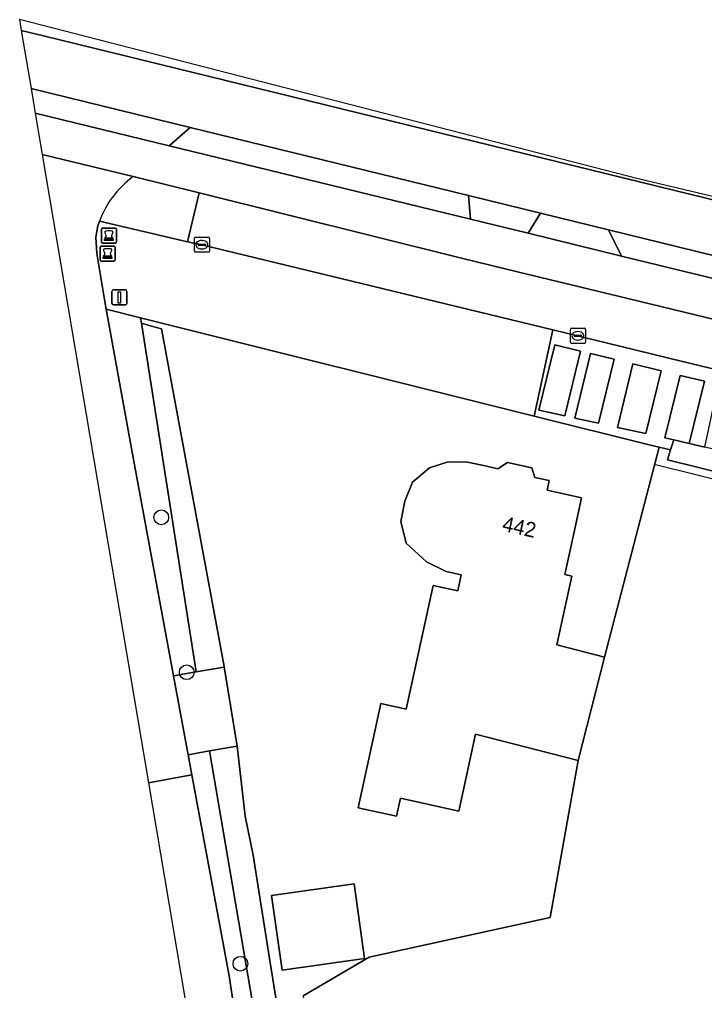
# Model space of a CAD drawing. Extents: x 163859 to 164644, y 379566 to 382155.
# Drawn here: x 164350.7 to 164396.2, y 382090.8 to 382155.2 of the extents above; entities that cross this region are included whole.
import ezdxf

# ---------------------------------------------------------------- set-up
doc = ezdxf.new("R2010")
doc.units = 0
for name, color, linetype in [('IMGEO_Berm_groen', 7, 'Continuous'), ('IMGEO_Bolder', 7, 'Continuous'), ('IMGEO_Boom', 7, 'Continuous'), ('IMGEO_Erf', 7, 'Continuous'), ('IMGEO_Fietspad_gesloten', 7, 'Continuous'), ('IMGEO_Fietspad_open', 7, 'Continuous'), ('IMGEO_Grasland_agrarisch', 7, 'Continuous'), ('IMGEO_Groenvoorziening', 7, 'Continuous'), ('IMGEO_Hek', 7, 'Continuous'), ('IMGEO_Kolk', 7, 'Continuous'), ('IMGEO_Pand', 7, 'Continuous'), ('IMGEO_Pand_nummerreeks', 7, 'Continuous'), ('IMGEO_Parkeervlak_open', 7, 'Continuous'), ('IMGEO_Rijbaan_lokaal_halfverhard', 7, 'Continuous'), ('IMGEO_Rijbaan_lokaal_open', 7, 'Continuous'), ('IMGEO_Rijbaan_regionaal_gesloten', 7, 'Continuous'), ('IMGEO_Verkeersbordpaal', 7, 'Continuous'), ('IMGEO_Verkeerseiland_groen', 7, 'Continuous'), ('IMGEO_Voetpad_open', 7, 'Continuous'), ('IMGEO_Waterloop', 7, 'Continuous')]:
    doc.layers.add(name, color=color, linetype=linetype)

msp = doc.modelspace()

# ---------------------------------------------------------------- linework, layer by layer
at = {"layer": 'IMGEO_Berm_groen'}
msp.add_lwpolyline([(164362.857, 382140.279), (164361.904, 382140.469), (164356.054, 382141.847), (164355.948, 382141.543), (164355.811, 382140.786), (164355.877, 382139.695), (164356.39, 382136.646), (164356.507, 382135.999), (164358.788, 382135.429), (164384.91, 382128.907), (164386.164, 382134.631)], close=True, dxfattribs=at)
at = {"layer": 'IMGEO_Bolder'}
for p, q in [((164356.185, 382140.455), (164356.185, 382141.296)), ((164356.185, 382141.296), (164356.185, 382140.455)), ((164356.26, 382141.38), (164357.101, 382141.38)), ((164357.101, 382141.38), (164356.26, 382141.38)), ((164357.185, 382141.305), (164357.185, 382140.464)), ((164357.185, 382140.464), (164357.185, 382141.305)), ((164357.11, 382140.38), (164356.269, 382140.38)), ((164356.269, 382140.38), (164357.11, 382140.38)), ((164356.968, 382140.71), (164356.393, 382140.71)), ((164356.103, 382139.268), (164356.103, 382140.109)), ((164356.103, 382140.109), (164356.103, 382139.268)), ((164356.178, 382140.193), (164357.019, 382140.193)), ((164357.019, 382140.193), (164356.178, 382140.193)), ((164357.103, 382140.118), (164357.103, 382139.277)), ((164357.103, 382139.277), (164357.103, 382140.118)), ((164357.028, 382139.193), (164356.187, 382139.193)), ((164356.187, 382139.193), (164357.028, 382139.193)), ((164356.886, 382139.523), (164356.311, 382139.523))]:
    msp.add_line(p, q, dxfattribs=at)
for points in [[(164356.393, 382140.66), (164356.968, 382140.66), (164356.968, 382140.558), (164356.393, 382140.558), (164356.393, 382140.66)], [(164356.311, 382139.473), (164356.886, 382139.473), (164356.886, 382139.371), (164356.311, 382139.371), (164356.311, 382139.473)]]:
    msp.add_lwpolyline(points, dxfattribs=at)
for centre, radius, start, end in [((164356.263, 382141.302), 0.0779, 92.4484, 184.28452), ((164356.263, 382141.302), 0.0779, 92.4484, 184.28452), ((164356.334, 382140.871), 0.172, 289.86634, 37.64837), ((164356.449, 382141.122), 0.0482, 119.11853, 182.6026), ((164356.479, 382141.121), 0.0781, 181.25999, 199.25687), ((164356.687, 382141.192), 0.297, 198.84879, 209.67889), ((164356.513, 382141.021), 0.168, 102.85353, 121.35376), ((164357.271, 382141.509), 0.962, 208.90947, 213.66044), ((164356.68, 382140.155), 1.049, 78.76924, 101.23076), ((164357.027, 382140.871), 0.172, 142.35163, 250.13366), ((164356.847, 382141.021), 0.168, 58.64624, 77.14647), ((164356.09, 382141.509), 0.962, 326.33956, 331.09053), ((164356.674, 382141.192), 0.297, 330.32111, 341.15121), ((164356.911, 382141.122), 0.0482, 357.3974, 60.88147), ((164356.881, 382141.121), 0.0781, 340.74313, 358.74001), ((164357.107, 382141.302), 0.0779, 2.4484, 94.28452), ((164357.107, 382141.302), 0.0779, 2.4484, 94.28452), ((164356.263, 382140.458), 0.0779, 182.4484, 274.28452), ((164356.263, 382140.458), 0.0779, 182.4484, 274.28452), ((164357.107, 382140.458), 0.0779, 272.4484, 4.28452), ((164357.107, 382140.458), 0.0779, 272.4484, 4.28452), ((164356.181, 382140.115), 0.0779, 92.4484, 184.28452), ((164356.181, 382140.115), 0.0779, 92.4484, 184.28452), ((164356.252, 382139.684), 0.172, 289.86634, 37.64837), ((164356.367, 382139.935), 0.0482, 119.11853, 182.6026), ((164356.397, 382139.934), 0.0781, 181.25999, 199.25687), ((164356.605, 382140.005), 0.297, 198.84879, 209.67889), ((164356.431, 382139.834), 0.168, 102.85353, 121.35376), ((164357.189, 382140.322), 0.962, 208.90947, 213.66044), ((164356.598, 382138.968), 1.049, 78.76924, 101.23076), ((164356.945, 382139.684), 0.172, 142.35163, 250.13366), ((164356.765, 382139.834), 0.168, 58.64624, 77.14647), ((164356.008, 382140.322), 0.962, 326.33956, 331.09053), ((164356.592, 382140.005), 0.297, 330.32111, 341.15121), ((164356.829, 382139.935), 0.0482, 357.3974, 60.88147), ((164356.799, 382139.934), 0.0781, 340.74313, 358.74001), ((164357.025, 382140.115), 0.0779, 2.4484, 94.28452), ((164357.025, 382140.115), 0.0779, 2.4484, 94.28452), ((164356.181, 382139.271), 0.0779, 182.4484, 274.28452), ((164356.181, 382139.271), 0.0779, 182.4484, 274.28452), ((164357.025, 382139.271), 0.0779, 272.4484, 4.28452), ((164357.025, 382139.271), 0.0779, 272.4484, 4.28452)]:
    msp.add_arc(centre, radius, start, end, dxfattribs=at)
at = {"layer": 'IMGEO_Boom'}
for centre in [(164360.159, 382122.182), (164361.852, 382111.898), (164365.415, 382092.55)]:
    msp.add_circle(centre, 0.489, dxfattribs=at)
at = {"layer": 'IMGEO_Erf'}
msp.add_lwpolyline([(164369.59, 382090.415), (164373.957, 382092.98), (164385.986, 382095.611), (164387.831, 382106.038), (164381.031, 382107.789), (164379.918, 382102.683), (164376.049, 382103.53), (164375.789, 382102.34), (164373.226, 382102.901), (164373.716, 382105.14), (164374.743, 382109.831), (164376.422, 382109.445), (164378.218, 382117.661), (164379.85, 382117.305), (164380.083, 382118.372), (164379.079, 382118.592), (164377.764, 382119.237), (164376.427, 382120.475), (164376.062, 382121.898), (164376.328, 382123.256), (164376.831, 382124.522), (164377.976, 382125.467), (164379.215, 382125.876), (164380.503, 382125.848), (164381.662, 382125.595), (164382.517, 382125.408), (164383.16, 382125.821), (164384.761, 382125.471), (164384.967, 382124.825), (164385.919, 382124.617), (164385.781, 382123.983), (164388.067, 382123.484), (164387.546, 382121.1), (164386.954, 382118.388), (164387.414, 382118.288), (164386.417, 382113.726), (164389.6, 382112.906), (164393.22, 382126.843), (164392.563, 382126.997), (164384.91, 382128.907), (164358.788, 382135.429), (164358.85, 382135.065), (164359.516, 382134.882), (164360.183, 382134.698), (164364.328, 382112.273), (164364.335, 382112.233), (164364.354, 382112.133), (164365.199, 382106.995), (164365.725, 382102.336), (164366.273, 382099.763), (164367.356, 382092.892), (164367.768, 382090.275)], dxfattribs=at)
msp.add_lwpolyline([(164373.663, 382092.9), (164368.177, 382092.124), (164367.477, 382097.076), (164372.963, 382097.852)], close=True, dxfattribs=at)
at = {"layer": 'IMGEO_Fietspad_gesloten'}
for points in [[(164351.794, 382149.021), (164352.259, 382146.273), (164358.291, 382144.799), (164362.677, 382143.726), (164380.086, 382139.395), (164383.897, 382138.464), (164391.868, 382136.525), (164462.951, 382119.296), (164479.662, 382115.151), (164500, 382110.112), (164547.275, 382098.592), (164553.371, 382097.107), (164566.017, 382094.025)], [(164566.608, 382096.623), (164500, 382112.869), (164480.06, 382117.733), (164432.227, 382129.4), (164397.276, 382137.925), (164390.718, 382139.524), (164384.514, 382141.037), (164380.701, 382141.967), (164360.676, 382146.852), (164351.794, 382149.021)]]:
    msp.add_lwpolyline(points, dxfattribs=at)
at = {"layer": 'IMGEO_Fietspad_open'}
msp.add_lwpolyline([(164351.518, 382150.649), (164351.794, 382149.021), (164360.676, 382146.852), (164362.069, 382148.073)], close=True, dxfattribs=at)
at = {"layer": 'IMGEO_Grasland_agrarisch'}
msp.add_lwpolyline([(164435.91, 382115.587), (164393.78, 382126.007), (164393.977, 382126.658), (164393.22, 382126.843), (164389.6, 382112.906), (164387.831, 382106.038), (164385.986, 382095.611), (164373.957, 382092.98), (164369.59, 382090.415), (164371.919, 382069.694), (164374.733, 382046.331), (164377.32, 382019.353)], dxfattribs=at)
at = {"layer": 'IMGEO_Groenvoorziening'}
msp.add_lwpolyline([(164358.85, 382135.065), (164358.788, 382135.429), (164356.507, 382135.999), (164358.266, 382126.263), (164360.971, 382111.652), (164362.476, 382111.931)], close=True, dxfattribs=at)
msp.add_lwpolyline([(164377.319, 381999.913), (164375.002, 382024.987), (164374.98, 382025.233), (164374.694, 382027.134), (164374.125, 382027.073), (164373.556, 382027.013), (164371.068, 382052.247), (164369.311, 382067.964), (164367.499, 382080), (164366.209, 382089.978), (164363.361, 382106.673), (164361.941, 382106.41), (164362.186, 382105.089), (164364.658, 382091.736), (164366.228, 382081.359), (164368.326, 382065.243), (164375.071, 382000), (164376.328, 381987.84), (164377.032, 381983.081), (164379.466, 381969.665), (164387.742, 381919.592), (164388.097, 381917.443), (164394.676, 381881.88)], dxfattribs=at)
at = {"layer": 'IMGEO_Hek'}
msp.add_lwpolyline([(164392.898, 382125.718), (164435.546, 382115.127)], dxfattribs=at)
at = {"layer": 'IMGEO_Kolk'}
for p, q in [((164362.356, 382139.854), (164362.356, 382140.706)), ((164362.431, 382140.78), (164363.283, 382140.78)), ((164362.615, 382140.274), (164362.615, 382140.286)), ((164363.053, 382140.237), (164362.655, 382140.237)), ((164362.658, 382140.323), (164363.056, 382140.323)), ((164362.844, 382140.56), (164362.869, 382140.56)), ((164363.099, 382140.286), (164363.099, 382140.274)), ((164363.357, 382140.706), (164363.357, 382139.854)), ((164363.283, 382139.78), (164362.431, 382139.78)), ((164362.867, 382140), (164362.842, 382140)), ((164387.322, 382133.804), (164387.322, 382134.656)), ((164387.397, 382134.73), (164388.249, 382134.73)), ((164387.81, 382134.51), (164387.835, 382134.51)), ((164388.323, 382134.656), (164388.323, 382133.804)), ((164387.581, 382134.224), (164387.581, 382134.236)), ((164388.019, 382134.187), (164387.621, 382134.187)), ((164387.624, 382134.273), (164388.022, 382134.273)), ((164387.833, 382133.95), (164387.808, 382133.95)), ((164388.065, 382134.236), (164388.065, 382134.224)), ((164388.249, 382133.73), (164387.397, 382133.73))]:
    msp.add_line(p, q, dxfattribs=at)
for points in [[(164362.356, 382139.854), (164362.356, 382140.706)], [(164362.431, 382140.78), (164363.283, 382140.78)], [(164363.357, 382140.706), (164363.357, 382139.854)], [(164363.283, 382139.78), (164362.431, 382139.78)], [(164387.322, 382133.804), (164387.322, 382134.656)], [(164387.397, 382134.73), (164388.249, 382134.73)], [(164388.323, 382134.656), (164388.323, 382133.804)], [(164388.249, 382133.73), (164387.397, 382133.73)]]:
    msp.add_lwpolyline(points, dxfattribs=at)
for centre, radius, start, end in [((164362.433, 382140.704), 0.0765, 91.55205, 178.44795), ((164362.433, 382140.704), 0.0765, 91.55205, 178.44795), ((164362.655, 382140.283), 0.0403, 85.87752, 175.75265), ((164362.652, 382140.273), 0.0366, 178.93798, 274.71019), ((164363.056, 382140.28), 0.043, 264.86636, 352.45326), ((164363.06, 382140.285), 0.0386, 1.73085, 96.63898), ((164363.281, 382140.704), 0.0765, 1.55205, 88.44795), ((164363.281, 382140.704), 0.0765, 1.55205, 88.44795), ((164362.433, 382139.856), 0.0765, 181.55205, 268.44795), ((164362.433, 382139.856), 0.0765, 181.55205, 268.44795), ((164363.281, 382139.856), 0.0765, 271.55205, 358.44795), ((164363.281, 382139.856), 0.0765, 271.55205, 358.44795), ((164387.399, 382134.654), 0.0765, 91.55205, 178.44795), ((164387.399, 382134.654), 0.0765, 91.55205, 178.44795), ((164388.247, 382134.654), 0.0765, 1.55205, 88.44795), ((164388.247, 382134.654), 0.0765, 1.55205, 88.44795), ((164387.399, 382133.806), 0.0765, 181.55205, 268.44795), ((164387.399, 382133.806), 0.0765, 181.55205, 268.44795), ((164387.621, 382134.233), 0.0403, 85.87752, 175.75265), ((164387.618, 382134.223), 0.0366, 178.93798, 274.71019), ((164388.022, 382134.23), 0.043, 264.86636, 352.45326), ((164388.026, 382134.235), 0.0386, 1.73085, 96.63898), ((164388.247, 382133.806), 0.0765, 271.55205, 358.44795), ((164388.247, 382133.806), 0.0765, 271.55205, 358.44795)]:
    msp.add_arc(centre, radius, start, end, dxfattribs=at)
for centre, major_axis, ratio, start_param, end_param in [((164362.843, 382140.28), (-0.387, 0.002), 0.722429, 4.712389, 7.853982), ((164362.868, 382140.28), (-0.39, 0.002), 0.717154, 1.570796, 4.712389), ((164387.809, 382134.23), (-0.387, 0.002), 0.722429, 4.712389, 7.853982), ((164387.834, 382134.23), (-0.39, 0.002), 0.717154, 1.570796, 4.712389)]:
    msp.add_ellipse(centre, major_axis=major_axis, ratio=ratio, start_param=start_param, end_param=end_param, dxfattribs=at)
at = {"layer": 'IMGEO_Pand'}
for points in [[(164387.414, 382118.288), (164386.954, 382118.388), (164387.546, 382121.1), (164388.067, 382123.484), (164385.781, 382123.983), (164385.919, 382124.617), (164384.967, 382124.825), (164384.761, 382125.471), (164383.16, 382125.821), (164382.517, 382125.408), (164381.662, 382125.595), (164380.503, 382125.848), (164379.215, 382125.876), (164377.976, 382125.467), (164376.831, 382124.522), (164376.328, 382123.256), (164376.062, 382121.898), (164376.427, 382120.475), (164377.764, 382119.237), (164379.079, 382118.592), (164380.083, 382118.372), (164379.85, 382117.305), (164378.218, 382117.661), (164376.422, 382109.445), (164374.743, 382109.831), (164373.716, 382105.14), (164373.226, 382102.901), (164375.789, 382102.34), (164376.049, 382103.53), (164379.918, 382102.683), (164381.031, 382107.789), (164387.831, 382106.038), (164389.6, 382112.906), (164386.417, 382113.726)], [(164367.477, 382097.076), (164368.177, 382092.124), (164373.663, 382092.9), (164372.963, 382097.852)]]:
    msp.add_lwpolyline(points, close=True, dxfattribs=at)
at = {"layer": 'IMGEO_Parkeervlak_open'}
for points in [[(164388, 382133.219), (164386.284, 382133.637), (164385.229, 382129.3), (164386.956, 382128.921)], [(164390.231, 382132.676), (164388.663, 382133.057), (164387.622, 382128.775), (164389.199, 382128.43)], [(164393.353, 382131.916), (164391.481, 382132.371), (164390.454, 382128.155), (164392.336, 382127.743)], [(164396.221, 382131.218), (164394.612, 382131.609), (164393.603, 382127.465), (164394.183, 382127.338), (164395.216, 382127.093)]]:
    msp.add_lwpolyline(points, close=True, dxfattribs=at)
at = {"layer": 'IMGEO_Rijbaan_lokaal_halfverhard'}
msp.add_lwpolyline([(164394.676, 381881.88), (164388.097, 381917.443), (164387.742, 381919.592), (164379.466, 381969.665), (164377.032, 381983.081), (164376.328, 381987.84), (164375.071, 382000), (164368.326, 382065.243), (164366.228, 382081.359), (164364.658, 382091.736), (164362.186, 382105.089), (164359.316, 382104.565), (164361.733, 382090.282), (164360.434, 382089.079)], dxfattribs=at)
at = {"layer": 'IMGEO_Rijbaan_lokaal_open'}
for points in [[(164358.291, 382144.799), (164352.259, 382146.273), (164359.316, 382104.565)], [(164359.316, 382104.565), (164362.186, 382105.089), (164361.941, 382106.41), (164360.971, 382111.652), (164358.266, 382126.263), (164356.507, 382135.999), (164356.39, 382136.646), (164355.877, 382139.695), (164355.811, 382140.786), (164355.948, 382141.543), (164356.054, 382141.847)]]:
    msp.add_lwpolyline(points, dxfattribs=at)
msp.add_lwpolyline([(164364.354, 382112.133), (164364.335, 382112.233), (164362.476, 382111.931), (164360.971, 382111.652), (164361.941, 382106.41), (164363.361, 382106.673), (164364.28, 382106.834), (164365.199, 382106.995)], close=True, dxfattribs=at)
msp.add_arc((164362.15, 382139.551), 6.514, 126.32819, 159.36275, dxfattribs=at)
at = {"layer": 'IMGEO_Rijbaan_regionaal_gesloten'}
for points in [[(164350.742, 382155.237), (164350.865, 382154.51), (164352.346, 382154.141), (164422.808, 382136.877), (164448.236, 382130.698), (164525.74, 382111.863), (164595.632, 382094.807), (164595.863, 382096.242), (164391.818, 382144.662), (164350.742, 382155.237)], [(164595.632, 382094.807), (164525.74, 382111.863), (164448.236, 382130.698), (164422.808, 382136.877), (164352.346, 382154.141), (164350.865, 382154.51), (164351.518, 382150.649), (164362.069, 382148.073), (164380.564, 382143.542), (164385.347, 382142.37), (164389.853, 382141.266), (164399.244, 382138.965), (164431.396, 382131.087), (164481.274, 382118.867), (164500, 382114.279), (164576.432, 382095.763), (164593.391, 382091.527), (164595.076, 382091.117), (164595.074, 382091.217), (164595.072, 382091.329), (164595.632, 382094.807)]]:
    msp.add_lwpolyline(points, dxfattribs=at)
at = {"layer": 'IMGEO_Verkeersbordpaal'}
for p, q in [((164356.886, 382136.385), (164356.886, 382137.185)), ((164356.886, 382137.185), (164356.886, 382136.385)), ((164356.986, 382137.285), (164357.776, 382137.285)), ((164357.776, 382137.285), (164356.986, 382137.285)), ((164357.876, 382137.185), (164357.876, 382136.385)), ((164357.876, 382136.385), (164357.876, 382137.185)), ((164357.776, 382136.285), (164356.986, 382136.285)), ((164356.986, 382136.285), (164357.776, 382136.285))]:
    msp.add_line(p, q, dxfattribs=at)
msp.add_lwpolyline([(164357.306, 382137.16), (164357.456, 382137.16), (164357.456, 382136.41), (164357.306, 382136.41), (164357.306, 382137.16)], dxfattribs=at)
for centre, start, end in [((164356.986, 382137.185), 90, 180), ((164356.986, 382137.185), 90, 180), ((164357.776, 382137.185), 0, 90), ((164357.776, 382137.185), 360, 90), ((164356.986, 382136.385), 180, 270), ((164356.986, 382136.385), 180, 270), ((164357.776, 382136.385), 270, 0), ((164357.776, 382136.385), 270, 0)]:
    msp.add_arc(centre, 0.1, start, end, dxfattribs=at)
at = {"layer": 'IMGEO_Verkeerseiland_groen'}
for points in [[(164362.069, 382148.073), (164360.676, 382146.852), (164380.701, 382141.967), (164380.564, 382143.542)], [(164389.853, 382141.266), (164385.347, 382142.37), (164384.514, 382141.037), (164390.718, 382139.524)]]:
    msp.add_lwpolyline(points, close=True, dxfattribs=at)
at = {"layer": 'IMGEO_Voetpad_open'}
msp.add_lwpolyline([(164356.054, 382141.847), (164361.904, 382140.469), (164362.677, 382143.726), (164358.291, 382144.799)], dxfattribs=at)
for points in [[(164391.868, 382136.525), (164383.897, 382138.464), (164380.086, 382139.395), (164362.677, 382143.726), (164361.904, 382140.469), (164362.857, 382140.279), (164386.164, 382134.631), (164391.611, 382133.307), (164393.95, 382132.737), (164397.339, 382131.912), (164437.356, 382122.165), (164462.152, 382116.088), (164462.951, 382119.296)], [(164380.701, 382141.967), (164384.514, 382141.037), (164385.347, 382142.37), (164380.564, 382143.542)], [(164389.853, 382141.266), (164390.718, 382139.524), (164397.276, 382137.925), (164399.244, 382138.965)], [(164391.611, 382133.307), (164386.164, 382134.631), (164384.91, 382128.907), (164392.563, 382126.997), (164393.22, 382126.843), (164393.977, 382126.658), (164394.183, 382127.338), (164393.603, 382127.465), (164394.612, 382131.609), (164396.221, 382131.218), (164395.216, 382127.093), (164396.25, 382126.848), (164397.339, 382131.912), (164393.95, 382132.737)], [(164386.956, 382128.921), (164385.229, 382129.3), (164386.284, 382133.637), (164388, 382133.219)], [(164389.199, 382128.43), (164387.622, 382128.775), (164388.663, 382133.057), (164390.231, 382132.676)], [(164391.481, 382132.371), (164393.353, 382131.916), (164392.336, 382127.743), (164390.454, 382128.155)]]:
    msp.add_lwpolyline(points, close=True, dxfattribs=at)
msp.add_arc((164362.15, 382139.551), 6.514, 126.32819, 159.36275, dxfattribs=at)
at = {"layer": 'IMGEO_Waterloop'}
for points in [[(164360.183, 382134.698), (164359.516, 382134.882), (164358.85, 382135.065), (164362.476, 382111.931), (164364.335, 382112.233), (164364.328, 382112.273)], [(164396.25, 382126.848), (164395.216, 382127.093), (164394.183, 382127.338), (164393.977, 382126.658), (164393.78, 382126.007), (164435.91, 382115.587), (164435.113, 382110.541), (164436.636, 382108.734), (164437.949, 382115.908), (164438.135, 382116.921)], [(164363.361, 382106.673), (164366.209, 382089.978), (164367.499, 382080), (164369.311, 382067.964), (164371.068, 382052.247), (164373.556, 382027.013), (164374.125, 382027.073), (164374.694, 382027.134), (164372.988, 382051.449), (164369.499, 382079.302), (164368.053, 382088.47), (164367.768, 382090.275), (164367.356, 382092.892), (164366.273, 382099.763), (164365.725, 382102.336), (164365.199, 382106.995), (164364.28, 382106.834)]]:
    msp.add_lwpolyline(points, close=True, dxfattribs=at)

# ---------------------------------------------------------------- texts
at = {"layer": 'IMGEO_Pand_nummerreeks'}
msp.add_text('442', height=1, rotation=347.6986, dxfattribs=at).set_placement((164382.742, 382121.29))

doc.saveas('drawing.dxf')
